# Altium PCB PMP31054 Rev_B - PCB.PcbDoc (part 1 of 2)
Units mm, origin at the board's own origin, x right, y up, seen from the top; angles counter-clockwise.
Board outline 89.28 x 61.72 mm, 4 copper layers (Top Layer, GND, Signal Layer 2, Bottom Layer), stack 2.134 mm thick; 58 components, 20 nets, 96 pads, 56 vias.
Unrouted connection lines stored in the file: 4.
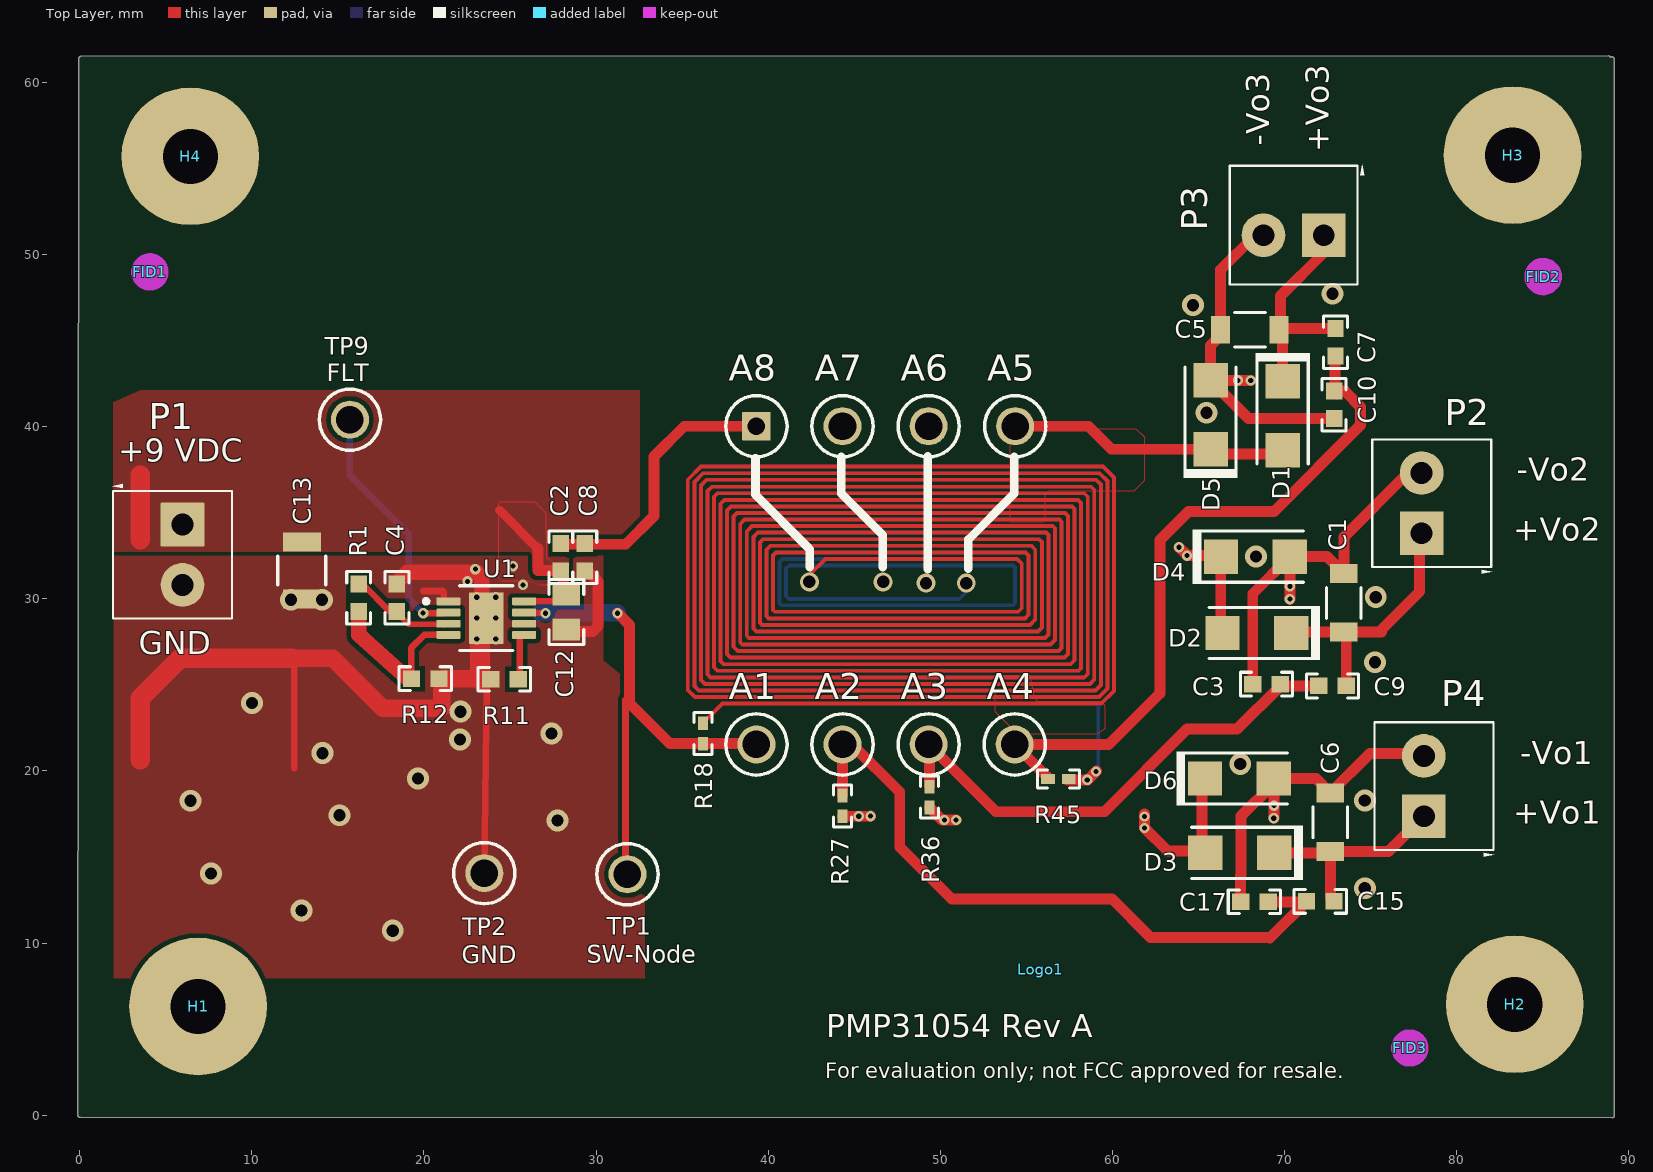
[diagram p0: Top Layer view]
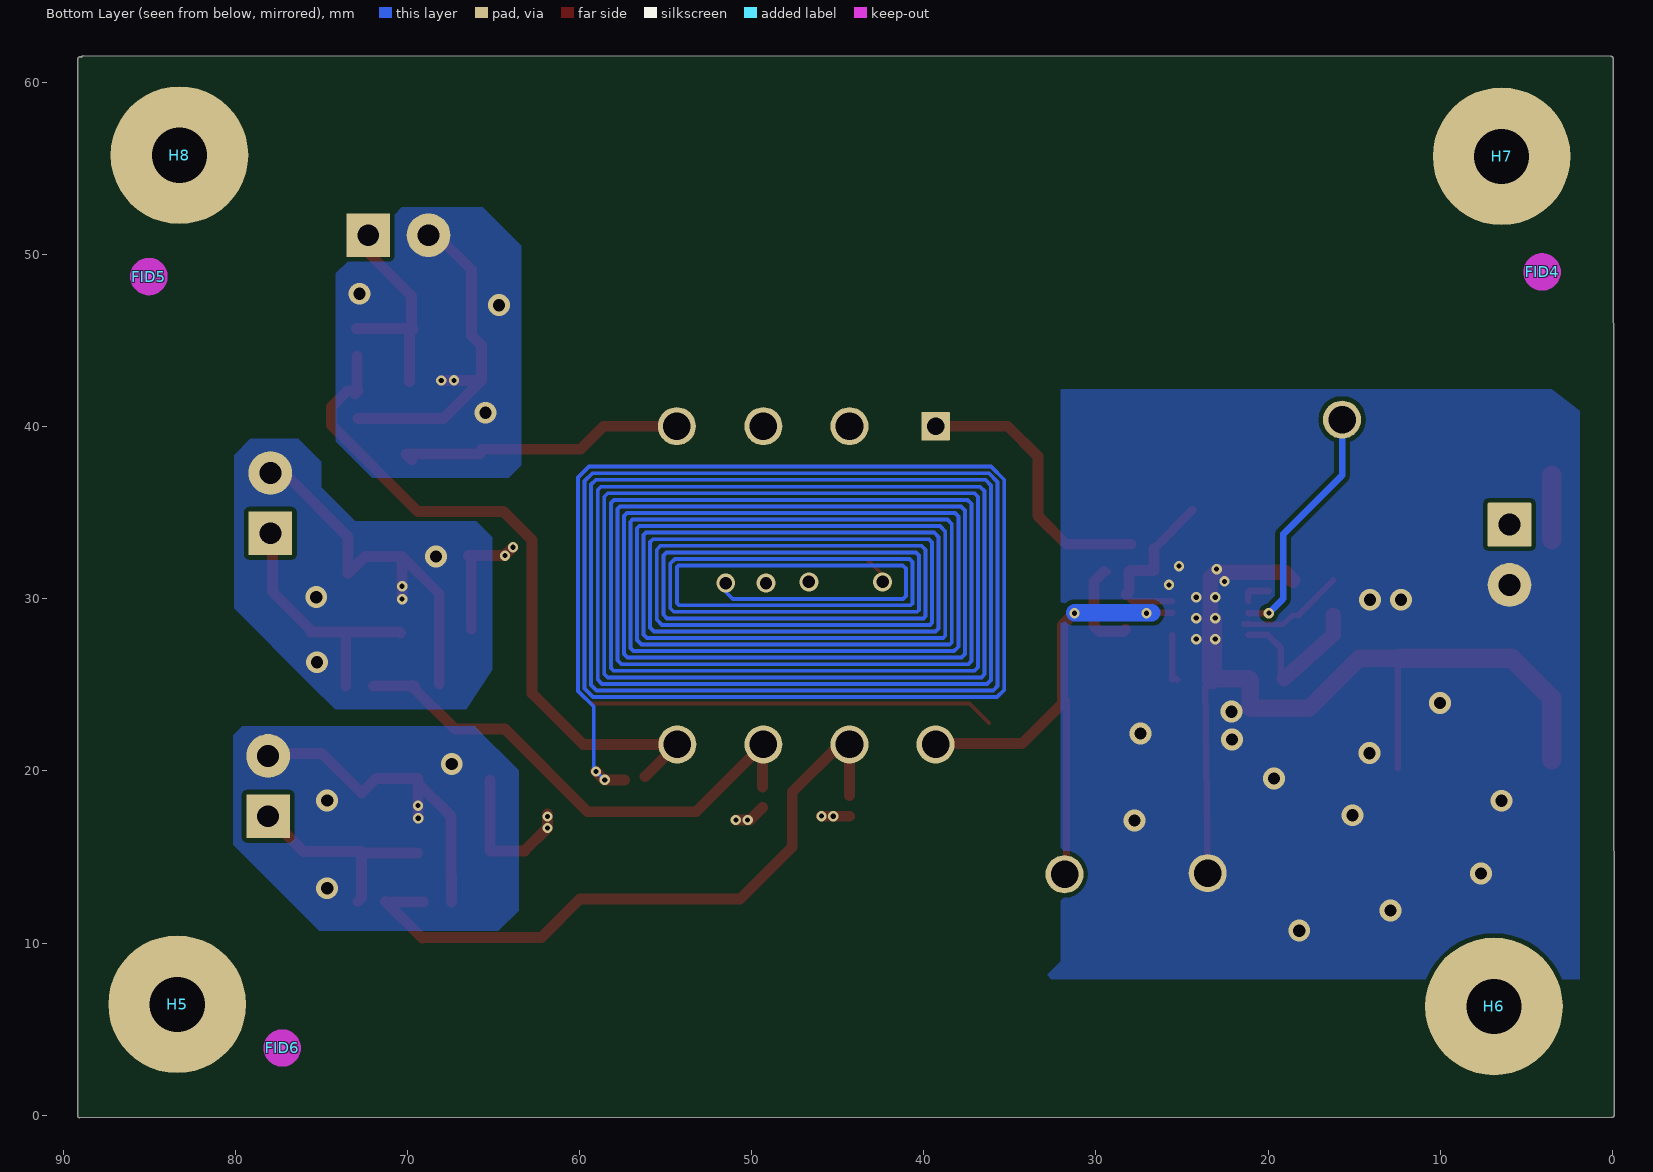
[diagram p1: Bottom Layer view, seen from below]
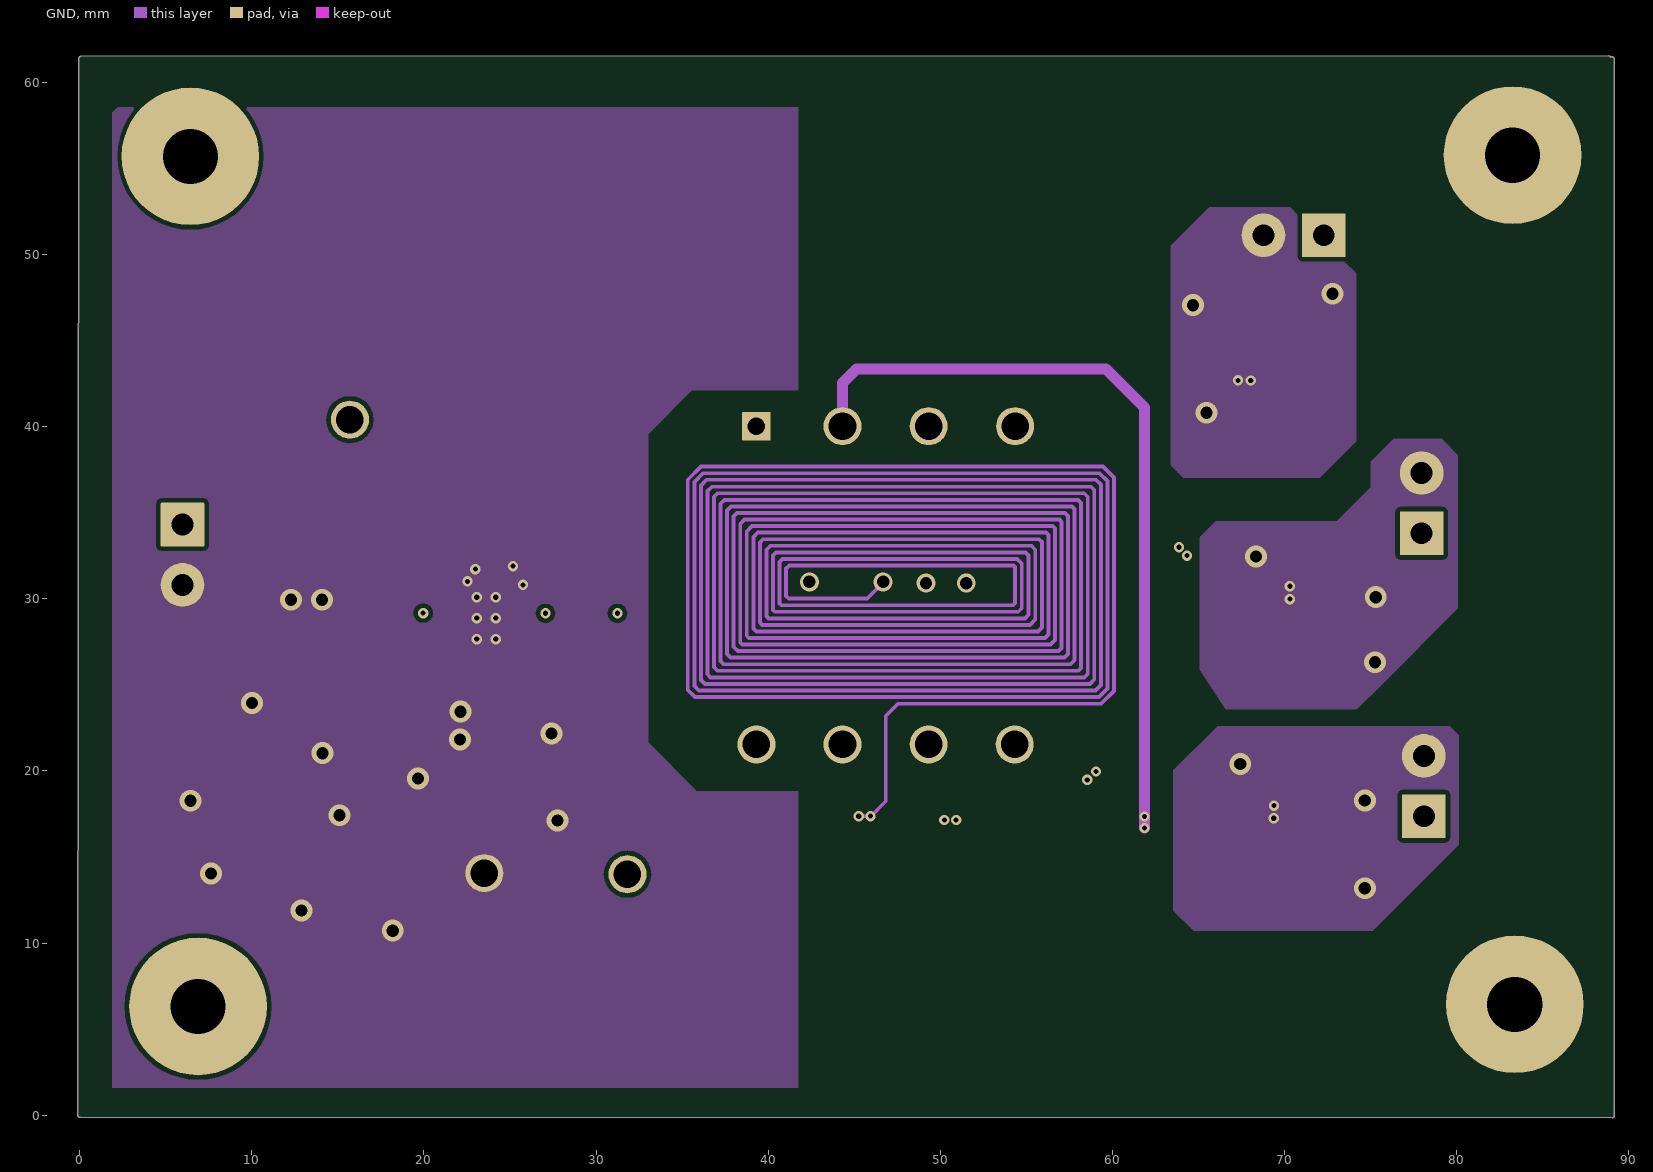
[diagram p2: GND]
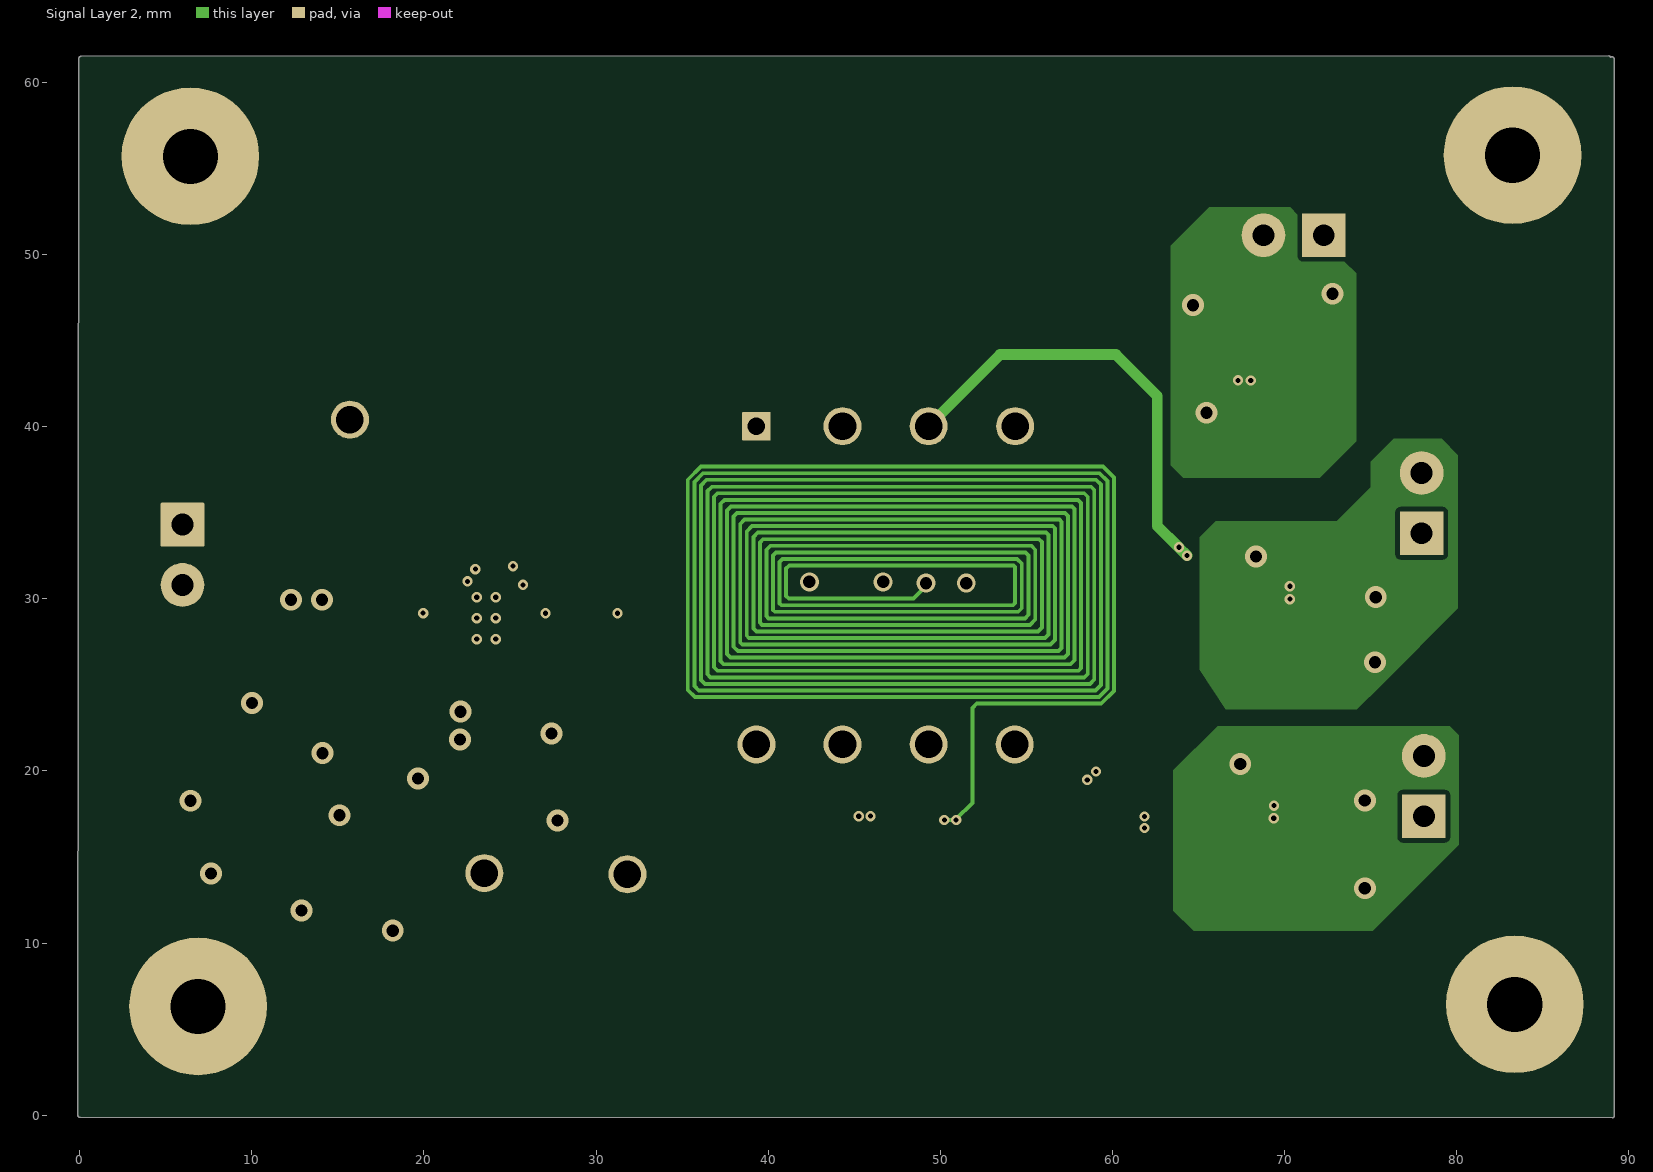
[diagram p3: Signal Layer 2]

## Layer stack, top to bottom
Top Solder: solder mask 0.0102, Solder Resist, Dk 3.5
Top Layer: signal copper 0.0356
Dielectric1: core 1.4834, FR-4 High Tg, Dk 4.8
GND: signal copper 0.036
Dielectric 2: dielectric 0.254, Dk 4.2
Signal Layer 2: signal copper 0.036
Dielectric 3: dielectric 0.254, Dk 4.2
Bottom Layer: signal copper 0.0356
Bottom Solder: solder mask 0.0102, Solder Resist, Dk 3.5

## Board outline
-0.116,-0.004 ccw(c0.011,-0.004) 0.011,-0.131 89.04,-0.165 ccw(c89.04,-0.038) 89.167,-0.038 89.167,61.366 ccw(c89.04,61.366) 88.959,61.465 ccw(c88.837,61.43) 88.836,61.557 0.075,61.523 ccw(c0.075,61.396) -0.053,61.396

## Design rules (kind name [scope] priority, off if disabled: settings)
AcuteAngle [All] p1: minimum=4.50000000000000E+0001 checktracksonly=FALSE
AssemblyTestPointUsage [All] p1: valid=2
BoardOutlineClearance BoardOutlineClearance_MountingHoles [OnCopper and InComponentClass('Mounting Holes')] p1: gap=1.016 ignorepadtopadclearanceinfootprint=FALSE
BoardOutlineClearance BoardOutlineClearance_Poly [OnCopper and IsPoly] p2: gap=0.635 ignorepadtopadclearanceinfootprint=FALSE except(0.254: Arc-CutoutEdge Track-CutoutEdge SMDPad-CutoutEdge THPad-CutoutEdge Via-CutoutEdge Fill-CutoutEdge Poly-CutoutEdge Region-CutoutEdge Text-CutoutEdge)
BoardOutlineClearance [OnCopper and Not InComponentClass('Logo') and not InComponentClass('FiducialMark') and not InRegion(1000,500,4000,800) and not InPoly] p3: gap=1.27 ignorepadtopadclearanceinfootprint=FALSE
Clearance Clearance_Keepouts [((IsTrack Or IsArc) And Not InPoly) And IsFree and IsKeepOut vs ((IsTrack Or IsArc) And Not InPoly) And IsFree and IsKeepOut] p1: gap=0 ignorepadtopadclearanceinfootprint=FALSE
Clearance Clearance_Poly [InPolygon] p2: gap=0.254 ignorepadtopadclearanceinfootprint=FALSE
Clearance Clearance_FiducialMark [IsKeepOut and InComponentClass('FiducialMark') vs IsPad and InComponentClass('FiducialMark')] p3: gap=0 ignorepadtopadclearanceinfootprint=FALSE
Clearance [All] p4: gap=0.2 ignorepadtopadclearanceinfootprint=FALSE except(0: Arc-Hole Track-Hole SMDPad-Hole THPad-Hole Via-Hole Fill-Hole Poly-Hole Region-Hole Text-Hole)
ComponentClearance ComponentClearance_NetTie [InComponent('NT1') vs HasFootprint('DSS0012C')] p1: gap=0 collisioncheckmode=3 verticalgap=0 showdistances=FALSE
ComponentClearance ComponentClearance_MountingHoles_FiducialMarks [InComponentClass('Mounting Holes') vs InComponentClass('FiducialMark')] p2: gap=1.27 collisioncheckmode=3 verticalgap=0.254 showdistances=FALSE
ComponentClearance ComponentClearance_Shunt [InComponentClass('Header') vs InComponentClass('Shunt')] p3: gap=0 collisioncheckmode=3 verticalgap=0 showdistances=FALSE
ComponentClearance ComponentClearance_Logo [InComponentClass('Logo')] p4: gap=1.27 collisioncheckmode=3 verticalgap=0.254 showdistances=FALSE
ComponentClearance ComponentClearance_ScrewToNut [(HasFootprint('NY PMS 440 0025 PH')) vs (HasFootprint('Keystone_1902C'))] p5: gap=0.127 collisioncheckmode=3 verticalgap=0.254 showdistances=FALSE
ComponentClearance ComponentClearance_MountingHoles [InComponentClass('Mounting Holes')] p6: gap=2.54 collisioncheckmode=3 verticalgap=2540 showdistances=FALSE
ComponentClearance ComponentClearance_SmallPassives [HasFootprint('0201*') or HasFootprint('0402*') or HasFootprint('0508') or HasFootprint('0603*') or HasFootprint('0612') or HasFootprint('0805*') or HasFootprint('0815*') or HasFootprint('0830*') or HasFootprint('1206*') or HasFootprint('1210*') or HasFootprint('1808*') or HasFootprint('1812*') or HasFootprint('1825*') or HasFootprint('2010*') or HasFootprint('2220*') or HasFootprint('2225*') or HasFootprint('2512*') or HasFootprint('2728*') or HasFootprint('3518*') vs HasFootprint('0201*') or HasFootprint('0402*') or HasFootprint('0508') or HasFootprint('0603*') or HasFootprint('0612') or HasFootprint('0805*') or HasFootprint('0815*') or HasFootprint('0830*') or HasFootprint('1206*') or HasFootprint('1210*') or HasFootprint('1808*') or HasFootprint('1812*') or HasFootprint('1825*') or HasFootprint('2010*') or HasFootprint('2220*') or HasFootprint('2225*') or HasFootprint('2512*') or HasFootprint('2728*') or HasFootprint('3518*')] p7: gap=0.38 collisioncheckmode=3 verticalgap=0.254 showdistances=FALSE
ComponentClearance ComponentClearance_THtoSMT [IsThruComponent vs IsSMTComponent] p8: gap=0.508 collisioncheckmode=3 verticalgap=0.762 showdistances=FALSE
ComponentClearance ComponentClearance_THtoTH [IsThruComponent vs IsThruComponent] p9: gap=0.508 collisioncheckmode=3 verticalgap=0.762 showdistances=FALSE
ComponentClearance [All] p10: gap=0.762 collisioncheckmode=3 verticalgap=0.254 showdistances=FALSE
DiffPairsRouting [All] p1: maxlimit=2.54 minlimit=0.254 mostfreqgap=0.254 toplayer_minwidth=0.381 toplayer_maxwidth=0.381 toplayer_prefwidth=0.381 midlayer1_minwidth=0.381 midlayer1_maxwidth=0.381 midlayer1_prefwidth=0.381 midlayer2_minwidth=0.381 midlayer2_maxwidth=0.381 midlayer2_prefwidth=0.381 bottomlayer_minwidth=0.381 bottomlayer_maxwidth=0.381 bottomlayer_prefwidth=0.381 maxuncoupledlength=25.4
FabricationTestPointUsage TestPointUsage [All] p1: valid=2 allowmultiple=FALSE
FabricationTestpoint Testpoint [All] p1: side=3 testpointundercomponent=TRUE minsize=1.016 maxsize=2.54 preferedsize=1.524 minholesize=0 maxholesize=1.016 preferedholesize=0.813 testpointgrid=0.025 allowsidetop=TRUE allowsidebottom=TRUE usegrid=TRUE gridtolerance=0
FanoutControl Fanout_LCC [IsLCC] p1: bgadir=Out bgaviamode=Centered fanoutstyle=Auto fanoutdirection=Alternating viagrid=0.025 // Fanout_LCC (Default Rule)
FanoutControl Fanout_BGA [IsBGA] p2: bgadir=Out bgaviamode=Centered fanoutstyle=Auto fanoutdirection=Alternating viagrid=0.025 // Fanout_BGA (Default Rule)
FanoutControl Fanout_Default [All] p4: bgadir=Out bgaviamode=Centered fanoutstyle=Auto fanoutdirection=Alternating viagrid=0.025 // Fanout_Default (Default Rule)
FanoutControl Fanout_Small [(CompPinCount < 5)] p5: bgadir=Out bgaviamode=Centered fanoutstyle=Auto fanoutdirection=OutThenIn viagrid=0.025 // Fanout_Small (Default Rule)
HoleSize [All] p1: absolutevalues=TRUE maxlimit=6.375 minlimit=0.3 maxpercent=80.000 minpercent=20.000
MinimumAnnularRing MinimumAnnularRing_ThermalPadVias [IsVia and InAnyComponent] p1: minimumring=0.15
MinimumAnnularRing [All] p2: minimumring=0.15
MinimumSolderMaskSliver MinimumSolderMaskSliver_Logo [InComponentClass('Logo') vs InComponentClass('Logo')] p1: minsoldermaskwidth=0.018
MinimumSolderMaskSliver [All] p2: minsoldermaskwidth=0.1
PlaneConnect [All] p1: planeconnectstyle=Relief reliefexpansion=0.254 reliefentries=4 reliefconductorwidth=0.254 reliefairgap=0.254
PolygonConnect [All] p1: connectstyle=Direct reliefconductorwidth=0.254 reliefentries=4 polygonreliefangle="90 Angle" airgapwidth=0.254
RoutingVias ThermalPadVias [IsVia and InAnyComponent] p1: holewidth=0.2 width=0.5 viastyle="Through Hole" minholewidth=0.2 minwidth=0.5 maxholewidth=0.33 maxwidth=0.6
RoutingVias [All] p2: holewidth=0.254 width=0.559 viastyle="Through Hole" minholewidth=0.2 minwidth=0.508 maxholewidth=1.016 maxwidth=1.651
SilkToBoardRegionClearance [Not ((IsComment or IsDesignator) And (Hide <> 'False')) and not InRegion(1000,500,4000,800)] p1:
SilkToSilkClearance SilkToSilkClearance_Pb-FreeLogo [(HasFootprint('Pb-Free_Overlay_Medium') OR HasFootprint('Pb-Free_Overlay_Small')) vs (HasFootprint('Pb-Free_Overlay_Medium') OR HasFootprint('Pb-Free_Overlay_Small'))] p1: silktosilkclearance=0
SilkToSilkClearance [All] p2: silktosilkclearance=0.102
SilkToSolderMaskClearance SilkToComponentPadClearance [(IsPad or IsFill or IsRegion) and InAnycomponent] p1: minsilkscreentomaskgap=0 clearancetoexposedcopper=TRUE
SilkToSolderMaskClearance "Silk to Solder Mask Opening" [All] p2: minsilkscreentomaskgap=0.102 clearancetoexposedcopper=FALSE
SolderMaskExpansion [All] p1: expansion=0.05 istentingtop=FALSE
Width [All] p1: maxlimit=2.54 minlimit=0.203 preferedwidth=0.381 checkconnectedcopper=TRUE
15 further rules are at their usual default settings.

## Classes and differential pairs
component class FiducialMark: FID1 FID2 FID3 FID4 FID5 FID6
component class "Mounting Holes": H1 H2 H3 H4
component class "PMP31054 Rev_B - hardware": !PCB FID1 FID2 FID3 FID4 FID5 FID6 H1 H2 H3 H4 H5 H6 H7 H8 LBL1 Logo1 Logo5
component class "PMP31054 Rev_B Sheet1": A1 A2 A3 A4 A5 A6 A7 A8 C1 C2 C3 C4 C5 C6 C7 C8 C9 C10 C12 C13 C15 C17 D1 D2 D3 D4 D5 D6 P1 P2 P3 P4 R1 R11 R12 R18 R27 R36 R45 TP1 TP2 TP9 U1

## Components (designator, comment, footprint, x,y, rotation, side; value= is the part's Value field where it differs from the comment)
A1 "5010" Keystone5010#1 39.319,21.539 r0 top
A2 "5010" Keystone5010#1 44.323,21.539 r0 top
A3 "5010" Keystone5010#1 49.327,21.539 r0 top
A4 "5010" Keystone5010#1 54.331,21.539 r0 top
A5 "5010" Keystone5010#1 54.356,40.03 r0 top
A6 "5010" Keystone5010#1 49.327,40.03 r0 top
A7 "5010" Keystone5010#1 44.323,40.03 r0 top
A8 "5010" Keystone5010#2 39.319,40.03 r0 top
C1 "885012108022" 1206_180 73.457,29.767 r90 top value=10uF
C2 "GRM188R71H153KA01D" 0603 27.953,32.41 r90 top value=0.015uF
C3 "CL10B822KB8NNNC" 0603 72.796,24.943 r180 top value=8200pF
C4 "C1608X7R1E105K080AB" 0603 18.428,30.061 r90 top value=1uF
C5 "885012108022" 1206_180 67.996,45.644 r180 top value=10uF
C6 "885012108022" 1206_180 72.669,17.018 r90 top value=10uF
C7 "CL10B822KB8NNNC" 0603 72.974,44.907 r270 top value=8200pF
C8 "GRM188R71H153KA01D" 0603 29.35,32.41 r270 top value=0.015uF
C9 "CL10B822KB8NNNC" 0603 68.961,25.044 r180 top value=8200pF
C10 "CL10B822KB8NNNC" 0603 72.89,41.275 r270 top value=8200pF
C12 "CGA4J3X7R1H225K125AB" 0805_HV 28.27,29.235 r270 top value=2.2uF
C13 "885012209073" 1210_280 12.903,31.648 r270 top value=10uF
C15 "CL10B822KB8NNNC" 0603 72.085,12.421 r180 top value=8200pF
C17 "CL10B822KB8NNNC" 0603 68.262,12.395 r180 top value=8200pF
D1 "CMSH1-40M TR13" SMA 69.901,40.64 r270 top value=40V
D2 "CMSH1-40M TR13" SMA 68.402,28.016 r180 top value=40V
D3 "CMSH1-40M TR13" SMA 67.412,15.24 r180 top value=40V
D4 "CMSH1-40M TR13" SMA 68.319,32.451 r0 top value=40V
D5 "CMSH1-40M TR13" SMA 65.71,40.691 r90 top value=40V
D6 "CMSH1-40M TR13" SMA 67.386,19.558 r0 top value=40V
FID1 "Fiducial" Fiducial6.4-20 4.077,48.997 r0 top
FID2 "Fiducial" Fiducial6.4-20 85.039,48.73 r0 top
FID3 "Fiducial" Fiducial6.4-20 77.292,3.899 r0 top
FID4 "Fiducial" Fiducial6.4-20 4.077,48.997 r180 bottom
FID5 "Fiducial" Fiducial6.4-20 85.039,48.73 r180 bottom
FID6 "Fiducial" Fiducial6.4-20 77.292,3.899 r180 bottom
H1 "NY PMS 440 0025 PH" "NY PMS 440 0025 PH" 6.871,6.312 r0 top
H2 "NY PMS 440 0025 PH" "NY PMS 440 0025 PH" 83.388,6.439 r0 top
H3 "NY PMS 440 0025 PH" "NY PMS 440 0025 PH" 83.261,55.778 r0 top
H4 "NY PMS 440 0025 PH" "NY PMS 440 0025 PH" 6.426,55.715 r0 top
H5 "1902C" Keystone_1902C 83.388,6.439 r180 bottom
H6 "1902C" Keystone_1902C 6.871,6.312 r180 bottom
H7 "1902C" Keystone_1902C 6.426,55.715 r180 bottom
H8 "1902C" Keystone_1902C 83.261,55.778 r180 bottom
Logo1 "FCC disclaimer" FCC_disclaimer 55.829,8.471 r0 top locked
P1 "ED555/2DS" TERM_BLK_ED555-2DS 5.969,34.315 r270 top
P2 "ED555/2DS" TERM_BLK_ED555-2DS 77.978,33.807 r90 top
P3 "ED555/2DS" TERM_BLK_ED555-2DS 72.288,51.13 r180 top
P4 "ED555/2DS" TERM_BLK_ED555-2DS 78.105,17.367 r90 top
R1 "CRCW06032K49FKEA" 0603 16.205,30.061 r90 top value=2.49k
R11 "CRCW0603100KFKEA" 0603 24.676,25.324 r0 top value=100k
R12 "CRCW06032K49FKEA" 0603 20.079,25.362 r180 top value=2.49k
R18 "ERJ2BWFR100X" 0402 36.22,22.174 r270 top value=0.1
R27 "ERJ2BWFR100X" 0402 44.323,17.967 r90 top value=0.1
R36 "ERJ2BWFR100X" 0402 49.378,18.475 r90 top value=0.1
R45 "ERJ2BWFR100X" 0402 56.871,19.533 r180 top value=0.1
TP1 "5010" Keystone5010#1 31.826,13.995 r90 top
TP2 "5011" Keystone5011 23.508,14.059 r90 top
TP9 "5010" Keystone5010#1 15.697,40.411 r0 top
U1 "UCC25800DGNRQ1" DGN0008G-MFG 23.622,28.877 r0 top

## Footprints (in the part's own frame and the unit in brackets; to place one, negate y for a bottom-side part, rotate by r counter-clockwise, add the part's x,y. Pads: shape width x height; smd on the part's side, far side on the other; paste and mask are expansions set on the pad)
0402 [mm] "0402 from SM-752 data"
  rect 0.8x0.6 smd: 1(-0.6,0) 2(0.6,0)
  silkscreen extent -1.22,-0.52 1.22,0.52, body extent -0.55,-0.3 0.55,0.3, height 0.6
0603 [mm] "0603 from SM-752 data"
  rect 1x0.95 smd: 1(-0.8,0) 2(0.8,0)
  silkscreen extent -1.52,-0.69 1.52,0.69, body extent -0.87,-0.47 0.87,0.47, height 1
0805_HV [mil] "0805 with 30mil clearance between pads"
  rect 50x63 smd: 1(-40,0) 2(40,0)
  silkscreen extent -74,-40 74,40, body extent -43,-29 43,29, height 57
1206_180 [mm] "1206_180"
  rect 1.1x1.6 smd: 1(-1.7,0) 2(1.7,0)
  silkscreen extent -0.9,-1 0.9,1, body extent -1.75,-0.95 1.75,0.95, height 1.8
1210_280 [mm] "SMD, 2-Leads, Body 3.6x2.8mm, Height 2.8mm"
  rect 1.1x2.2 smd: 1(-1.65,0) 2(1.65,0)
  silkscreen extent -0.84,-1.4 0.84,1.4, body extent -1.8,-1.4 1.8,1.4, height 2.8
DGN0008G-MFG [mm]
  rrect22% 1.4x0.45 smd paste+0 mask+0: 1(-2.2,0.975) 2(-2.2,0.325) 3(-2.2,-0.325) 4(-2.2,-0.975) 5(2.2,-0.975) 6(2.2,-0.325) 7(2.2,0.325) 8(2.2,0.975)
  rrect5% 2x3 smd paste-1000 mask-1000: 9(0,0)
  silkscreen extent -3.62,-1.88 1.55,1.88, body extent -3,-1.8 3,1.8, height 0.25
FCC_disclaimer [mm]
Fiducial6.4-20 [mm]
  round 0.635 smd mask+0.683: 1(0,0)
  Top Layer keep-out circle w1.178: c0,0 r0.5
Keystone5010#1 [mil] "Keystone Multipurpose loops"
  round 87 hole 63: 1(0,0)
  silkscreen extent -70,-70 70,70, body extent -63,-63 63,62, height 319
Keystone5010#2 [mil] "Keystone Multipurpose loops"
  rrect6% 64.96x64.96 hole 40: 1(0,0)
  silkscreen extent -70,-70 70,70, body extent -63,-63 63,62, height 319
Keystone5011 [mil] "Keystone Multipurpose loops"
  round 87 hole 63: 1(0,0)
  silkscreen extent -70,-70 70,70, body extent -63,-63 63,62, height 319
Keystone_1902C [mil] "Hex Standoff, 4-40 threaded, nylon"
  round 1 on Mech4: 0(0,0)
  body extent -145,-126 146,126, height 501
"NY PMS 440 0025 PH" [mm] "4-40 nylon screw and mounting hole"
  round 8 hole 3.2: 1(0,0)
  body extent -3.3,-3.3 3.3,3.3, height 2.69
SMA [mm] "Molded Diode, 2-Leads, Body 4.3x2.6mm, IPC Medium Density, based on OnSemi component dimensions and land pattern"
  rect 2x2 smd: 1(-2,0) 2(2,0)
  silkscreen extent -3.66,-1.57 2.79,1.57, body extent -2.6,-1.3 2.6,1.3, height 2.42
TERM_BLK_ED555-2DS [mil]
  rrect4% 100x100 hole 50: 1(0,0)
  round 100 hole 50: 2(138,0)
  silkscreen extent -93,-161 215,113, body extent -69,-150 207,106, height 323

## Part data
A1 A2 A3 A4 A5 A6 A7 A8 TP1 TP9: library part CMP-0055147-1, "Test Point, Multipurpose, Red, TH", Color=Red, Manufacturer=Keystone, Supplier Part Number 1=36-5010-ND
C1 C5 C6: library part CMP-0081454-1, "CAP, CERM, 10 µF, 50 V,+/- 20%, X5R, 1206", Cap_Case=1206, Manufacturer="Wurth Elektronik", TempCo=X5R, Tolerance_%=20%, Value2=50V, ValueDisplayed=10µF
C2 C8: library part CMP-0007438-4, "CAP, CERM, 0.015 uF, 50 V, +/- 10%, X7R, 0603", Cap_Case=0603, Manufacturer=MuRata, Supplier Part Number 1=490-1514-1-ND, TempCo=X7R, Tolerance_%=10%, Value1=Unknown, Value2=50V, ValueDisplayed=0.015uF
C3 C7 C9 C10 C15 C17: library part CMP-0860998-1, "CAP, CERM, 8200 pF, 50 V,+/- 10%, X7R, 0603", Cap_Case=0603, Manufacturer="Samsung Electro-Mechanics", TempCo=X7R, Tolerance_%=10%, Value2=50V, ValueDisplayed=8200pF
C4: library part CMP-0007040-4, "CAP, CERM, 1 uF, 25 V, +/- 10%, X7R, 0603", Cap_Case=0603, Manufacturer=TDK, Supplier Part Number 1=445-5956-1-ND, TempCo=X7R, Tolerance_%=10%, Value1=Unknown, Value2=25V, ValueDisplayed=1uF
C12: library part CMP-0007977-1, "CAP, CERM, 2.2 uF, 50 V, +/- 10%, X7R, AEC-Q200 Grade 1, 0805", Cap_Case=0805, Manufacturer=TDK, Supplier Part Number 1=445-174216-1-ND, TempCo=X7R, Tolerance_%=10%, Value1="0.003288 ohm", Value2=50V, ValueDisplayed=2.2uF
C13: library part CMP-0085350-1, "CAP, CERM, 10 µF, 50 V,+/- 10%, X7S, AEC-Q200 Grade 1, 1210", Cap_Case=1210, Manufacturer=TDK, PartNumber=CGA6P3X7S1H106K250AE, TempCo=X7S, Tolerance_%=10%, Value2=50V, ValueDisplayed=10µF
D1 D2 D3 D4 D5 D6: library part CMP-0028785-1, "Diode Schottky 40V 1A Surface Mount SMA", Manufacturer="Diodes Inc.", Value1=3A, Value2=0.7V
FID1 FID2 FID3 FID4 FID5 FID6: library part CMP-0077181-1, "Fiducial mark.  There is nothing to buy or mount.", Manufacturer=N/A
H1 H2 H3 H4: library part CMP-0003617-1, "Machine Screw, Round, #4-40 x 1/4, Nylon, Philips panhead", Manufacturer="B&F Fastener Supply", Supplier Part Number 1=H542-ND
H5 H6 H7 H8: library part CMP-0003610-1, "Standoff, Hex, 0.5\"L #4-40 Nylon", Manufacturer=Keystone, Supplier Part Number 1=36-1902C-ND
Logo1: library part CMP-0074847-1, "FCC_disclaimer"
P1 P2 P3 P4: library part CMP-0074913-1, "Terminal Block, 3.5mm Pitch, 2x1, TH", Color=Grey, Current_A=6A, Manufacturer="On-Shore Technology", Supplier Part Number 1=ED1514-ND, Voltage_V=150V
R1 R12: library part CMP-0022277-4, "RES, 2.49 k, 1%, 0.1 W, AEC-Q200 Grade 0, 0603", Manufacturer=Vishay-Dale, Power_W=100mW, Supplier Part Number 1=541-2.49KHCT-ND, TempCo="100 ppm/C", Tolerance_%=1%, Value2=0.1W, Value_Code=2k49, ValueDisplayed=2.49k
R11: library part CMP-0021990-4, "RES, 100 k, 1%, 0.1 W, AEC-Q200 Grade 0, 0603", Manufacturer=Vishay-Dale, Power_W=100mW, Supplier Part Number 1=541-100KHCT-ND, TempCo="100 ppm/C", Tolerance_%=1%, Value2=0.1W, Value_Code=100k
R18 R27 R36 R45: library part CMP-0078660-1, "RES, 0.1, 1%, 0.25 W, 0402", Manufacturer=Panasonic, Power_W=250mW, Supplier Part Number 1=P17368CT-ND, TempCo="300 ppm/C", Tolerance_%=1%, Value2=0.25W, Value_Code=R100, ValueDisplayed=0.1
TP2: library part CMP-0055148-1, "Test Point, Multipurpose, Black, TH", Color=Black, Manufacturer=Keystone, Supplier Part Number 1=36-5011-ND
U1: library part CMP-0088494-2, "Open Loop LLC Transformer Driver for Isolated Bias Supplies", Manufacturer="Texas Instruments", Max Supply Voltage=36V, Min Supply Voltage=12V, Nominal Supply Current=500uA, Operating Temperature Range="-40°C to +150°C", Switching Frequency=100-2000kHz

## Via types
v1: diameter 0.6, hole 0.3, Top Layer to Bottom Layer, 29 vias
v2: diameter 1.27, hole 0.711, Top Layer to Bottom Layer, 23 vias
v3: diameter 1.1, hole 0.71, Top Layer to Bottom Layer, 4 vias

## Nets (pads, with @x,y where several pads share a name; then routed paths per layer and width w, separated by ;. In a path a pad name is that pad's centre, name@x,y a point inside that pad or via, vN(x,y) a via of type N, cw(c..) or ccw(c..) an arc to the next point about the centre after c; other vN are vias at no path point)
GND: C4.2 C8.2 C12.2 C13.2 P1.2 R11.1 R12.1 TP2.1 U1.1 U1.6 U1.9 | length 64
  Top Layer w0.381: 12.331,26.545 12.459,26.417 12.459,20.145 ; C4.2@18.428,31.077 C4.2@18.555,31.077 ; 19.952,30.455 21.082,30.455 21.158,30.378 U1.1@21.158,29.852 ; 21.012,23.647 21.031,23.666 ; R12.1@21.031,25.298 R12.1@21.095,25.362 ; 23.19,25.362 23.254,25.298 23.644,24.908 TP2.1@23.508,14.059 ; U1.9@23.358,28.877 23.254,28.772 U1.9@23.474,28.552 ; C8.2@29.286,31.585 C8.2@29.54,31.585
  Top Layer w0.635: C12.2@28.27,28.219 28.397,28.092 29.794,28.092 30.112,28.41 30.112,31.013 C8.2@29.54,31.585
  Top Layer w0.889: C4.2@18.555,31.077 19.023,31.545 21.095,31.545 23.063,31.545 23.358,31.25 U1.9@23.358,28.877
  Top Layer w1.016: 12.331,26.545 14.705,26.545 17.602,23.647 21.012,23.647 ; 21.031,23.666 R12.1@21.031,25.298 ; R12.1@21.095,25.362 23.19,25.362
  Top Layer w1.143: 3.505,20.663 3.505,24.219 5.831,26.545 12.331,26.545 ; 23.254,25.298 U1.9@23.254,28.772
  other v1: 23.072,27.657 24.172,27.657 23.072,28.877 24.172,28.877 23.072,30.097 24.172,30.097 25.756,30.81 22.53,31.013 22.987,31.725 25.171,31.902
  other v2: 18.186,10.719 12.878,11.887 7.62,14.046 27.762,17.12 15.088,17.424 6.426,18.263 19.66,19.558 14.097,21.031 22.098,21.819 27.407,22.174 22.123,23.444 10.008,23.952 12.281,29.947 14.072,29.947
NetA1_1: A1.1 R18.2 TP1.1 U1.7 | length 30.1
  Top Layer w0.381: U1.7@25.558,29.202 U1.7@25.822,29.202 26.746,29.202 ; TP1.1@31.826,13.995 31.711,14.11 31.711,24.142 31.953,24.384 ; A1.1@39.194,21.582 39.278,21.498 A1.1@39.319,21.539
  Top Layer w0.5: v1(31.245,29.159) v1@31.258,29.172
  Top Layer w0.635: v1@31.258,29.172 31.953,28.477 31.953,24.52 31.953,24.384 ; 31.953,24.296 31.953,23.936 34.307,21.582 A1.1@39.194,21.582
  Bottom Layer w1.016: 26.746,29.202 v1@31.245,29.202
  other v1: 27.064,29.159
NetA2_1: A2.1 C15.2 C17.1 R27.2 | length 39.2
  Top Layer w0.635: R27.2@44.323,18.567 A2.1@44.323,21.539 44.882,21.539 47.65,18.771 47.65,15.57 50.673,12.548 59.995,12.548 62.23,10.312 69.177,10.312 ; C17.1@69.062,12.395 C15.2@70.942,12.395 ; 69.151,10.287 69.177,10.312 ; C15.2@71.285,12.421 69.177,10.312
NetA3_1: A3.1 C3.2 C9.1 R36.2 | length 29.9
  Top Layer w0.635: A3.1@49.327,21.539 A3.1@49.378,21.488 ; R36.2@49.378,19.075 A3.1@49.378,21.488 ; C9.1@69.596,24.943 C9.1@69.767,24.943 ; C9.1@69.787,24.963 C9.1@69.767,24.943 ; C3.2@71.996,24.943 C9.1@69.767,24.943 ; A3.1@49.378,21.488 53.238,17.628 59.538,17.628 64.338,22.428 67.252,22.428 C9.1@69.767,24.943
NetA4_1: A4.1 C7.2 C10.1 R45.2 | length 41.1
  Top Layer w0.225: R45.2@56.194,19.482 R45.2@56.194,19.675
  Top Layer w0.635: R45.2@56.194,19.675 A4.1@54.331,21.539 59.792,21.539 62.763,24.511 62.763,33.415 64.426,35.077 69.409,35.077 74.43,40.099 74.43,41.156 73.511,42.075 C10.1@73.055,42.075 ; C7.2@72.949,44.107 72.949,42.181 C10.1@73.055,42.075 ; C10.1@73.056,41.909 C10.1@72.89,42.075 C10.1@73.055,42.075
NetA5_1: A5.1 D1.2 D5.1 R45.1 | length 868.5
  Top Layer w0.225: A5.1@54.007,39.681 A5.1@54.356,40.03
  Top Layer w0.635: A5.1@54.356,40.03 58.623,40.03 59.963,38.691 D5.1@65.71,38.691 ; R45.1@57.394,19.482 v1(58.547,19.482) 58.572,19.482 v1@59.08,19.99 ; D5.1@65.786,38.405 70.097,38.405 D1.2@69.748,38.056
  Bottom Layer w0.225: v3@51.587,31.217 51.664,31.14 51.511,30.988 v3(51.511,30.912) 51.511,30.404 51.105,29.997 41.213,29.997 41.046,30.164 41.046,31.764 41.224,31.942 54.254,31.942 54.356,31.84 54.356,29.758 54.228,29.63 40.767,29.63 40.665,29.732 40.665,32.145 40.843,32.323 54.458,32.323 54.737,32.043 54.737,29.452 54.534,29.249 40.386,29.249 40.284,29.351 40.284,32.526 40.462,32.704 54.96,32.704 55.138,32.526 55.138,29.077 54.93,28.868 40.03,28.868 39.903,28.995 39.903,32.856 40.132,33.085 55.296,33.085 55.524,32.856 55.524,28.792 55.22,28.487 39.649,28.487 39.522,28.614 39.522,33.284 39.702,33.464 55.751,33.464 55.905,33.309 55.905,28.335 55.677,28.106 39.319,28.106 39.141,28.284 39.141,33.593 39.395,33.847 56.147,33.847 56.286,33.707 56.286,27.928 56.083,27.725 38.887,27.725 38.76,27.852 38.76,33.923 39.065,34.228 56.54,34.228 56.667,34.101 56.667,27.598 56.413,27.344 38.506,27.344 38.379,27.471 38.379,34.355 38.633,34.609 56.921,34.609 57.048,34.482 57.048,27.141 56.871,26.963 38.252,26.963 37.998,27.217 37.998,34.786 38.202,34.99 57.252,34.99 57.429,34.812 57.429,26.785 57.226,26.582 37.821,26.582 37.617,26.785 37.617,35.142 37.846,35.371 57.658,35.371 57.81,35.218 57.81,26.43 57.582,26.201 37.414,26.201 37.236,26.379 37.236,35.525 37.461,35.75 58.014,35.75 58.191,35.572 58.191,25.973 58.039,25.82 37.059,25.82 36.855,26.023 36.855,35.929 37.059,36.133 58.369,36.133 58.572,35.929 58.572,25.642 58.369,25.439 36.652,25.439 36.474,25.617 36.474,36.26 36.728,36.514 58.776,36.514 58.953,36.336 58.953,25.312 58.699,25.058 36.322,25.058 36.093,25.287 36.093,36.59 36.424,36.92 59.055,36.92 59.334,36.641 59.334,24.982 59.03,24.677 35.966,24.677 35.715,24.928 35.715,36.796 36.216,37.296 59.263,37.296 59.715,36.844 59.715,24.779 59.233,24.296 35.741,24.296 35.331,24.706 35.331,36.92 36.093,37.682 59.461,37.682 60.096,37.047 60.096,24.652 59.182,23.737 59.182,20.117 v1(58.547,19.482)
  other v1: 59.055,19.964
NetA6_1: A6.1 D2.2 D4.1 R36.1 | length 891.8
  Top Layer w0.225: D4.1@66.301,32.432 D4.1@66.319,32.451
  Top Layer w0.635: R36.1@49.378,17.875 50.108,17.145 v1(50.241,17.145) v1(50.927,17.145) ; v1(63.881,32.995) 64.338,32.537 v1(64.338,32.512) D4.1@66.478,32.512 ; D2.2@66.301,28.26 D4.1@66.301,32.432
  Signal Layer 2 w0.225: v3(49.174,30.912) 49.174,30.736 48.449,30.011 41.199,30.011 41.046,30.164 41.046,31.764 41.224,31.942 54.254,31.942 54.356,31.84 54.356,29.758 54.228,29.63 40.767,29.63 40.665,29.732 40.665,32.145 40.843,32.323 54.458,32.323 54.737,32.043 54.737,29.452 54.534,29.249 40.386,29.249 40.284,29.351 40.284,32.526 40.462,32.704 54.96,32.704 55.138,32.526 55.138,29.077 54.93,28.868 40.03,28.868 39.903,28.995 39.903,32.856 40.132,33.085 55.296,33.085 55.524,32.856 55.524,28.792 55.22,28.487 39.649,28.487 39.522,28.614 39.522,33.284 39.702,33.464 55.751,33.464 55.905,33.309 55.905,28.335 55.677,28.106 39.319,28.106 39.141,28.284 39.141,33.593 39.395,33.847 56.147,33.847 56.286,33.707 56.286,27.928 56.083,27.725 38.887,27.725 38.76,27.852 38.76,33.923 39.065,34.228 56.54,34.228 56.667,34.101 56.667,27.598 56.413,27.344 38.506,27.344 38.379,27.471 38.379,34.355 38.633,34.609 56.921,34.609 57.048,34.482 57.048,27.141 56.871,26.963 38.252,26.963 37.998,27.217 37.998,34.786 38.202,34.99 57.252,34.99 57.429,34.812 57.429,26.785 57.226,26.582 37.821,26.582 37.617,26.785 37.617,35.142 37.846,35.371 57.658,35.371 57.81,35.218 57.81,26.43 57.582,26.201 37.414,26.201 37.236,26.379 37.236,35.525 37.461,35.75 58.014,35.75 58.191,35.572 58.191,25.973 58.039,25.82 37.059,25.82 36.855,26.023 36.855,35.929 37.059,36.133 58.369,36.133 58.572,35.929 58.572,25.642 58.369,25.439 36.652,25.439 36.474,25.617 36.474,36.26 36.728,36.514 58.776,36.514 58.953,36.336 58.953,25.312 58.699,25.058 36.322,25.058 36.093,25.287 36.093,36.59 36.424,36.92 59.055,36.92 59.334,36.641 59.334,24.982 59.03,24.677 35.966,24.677 35.715,24.928 35.715,36.796 36.216,37.296 59.263,37.296 59.715,36.844 59.715,24.779 59.233,24.296 35.741,24.296 35.331,24.706 35.331,36.92 36.093,37.682 59.461,37.682 60.096,37.047 60.096,24.652 59.36,23.915 52.121,23.915 51.867,23.661 51.867,18.136 50.927,17.196 v1(50.927,17.145) v1(50.241,17.145)
  Signal Layer 2 w0.635: A6.1@49.327,40.03 53.486,44.19 60.204,44.19 62.611,41.783 62.611,34.239 v1@63.868,32.982 ; v1(63.881,32.995) 63.881,32.969 v1(64.338,32.512)
NetA7_1: A7.1 D3.2 D6.1 R27.1 | length 915.4
  Top Layer w0.215: A7.1@44.323,39.827 A7.1@44.323,40.03
  Top Layer w0.225: D6.1@65.208,19.475 D6.1@65.24,19.507
  Top Layer w0.635: R27.1@44.323,17.367 v1@45.339,17.367 ; v1(45.263,17.367) 45.942,17.367 v1(45.949,17.374) ; v1@61.874,17.501 v1(61.874,16.688) 63.195,15.367 ; 63.195,15.342 65.208,15.342 D6.1@65.208,19.475
  GND w0.225: v1(45.263,17.367) 45.968,17.367 46.838,18.237 46.838,23.19 47.549,23.901 59.346,23.901 60.096,24.652 60.096,37.047 59.461,37.682 36.093,37.682 35.331,36.92 35.331,24.706 35.741,24.296 59.233,24.296 59.715,24.779 59.715,36.844 59.263,37.296 36.216,37.296 35.715,36.796 35.715,24.928 35.966,24.677 59.03,24.677 59.334,24.982 59.334,36.641 59.055,36.92 36.424,36.92 36.093,36.59 36.093,25.287 36.322,25.058 58.699,25.058 58.953,25.312 58.953,36.336 58.776,36.514 36.728,36.514 36.474,36.26 36.474,25.617 36.652,25.439 58.369,25.439 58.572,25.642 58.572,35.929 58.369,36.133 37.059,36.133 36.855,35.929 36.855,26.023 37.059,25.82 58.039,25.82 58.191,25.973 58.191,35.572 58.014,35.75 37.461,35.75 37.236,35.525 37.236,26.379 37.414,26.201 57.582,26.201 57.81,26.43 57.81,35.218 57.658,35.371 37.846,35.371 37.617,35.142 37.617,26.785 37.821,26.582 57.226,26.582 57.429,26.785 57.429,34.812 57.252,34.99 38.202,34.99 37.998,34.786 37.998,27.217 38.252,26.963 56.871,26.963 57.048,27.141 57.048,34.482 56.921,34.609 38.633,34.609 38.379,34.355 38.379,27.471 38.506,27.344 56.413,27.344 56.667,27.598 56.667,34.101 56.54,34.228 39.065,34.228 38.76,33.923 38.76,27.852 38.887,27.725 56.083,27.725 56.286,27.928 56.286,33.707 56.147,33.847 39.395,33.847 39.141,33.593 39.141,28.284 39.319,28.106 55.677,28.106 55.905,28.335 55.905,33.309 55.751,33.464 39.702,33.464 39.522,33.284 39.522,28.614 39.649,28.487 55.22,28.487 55.524,28.792 55.524,32.856 55.296,33.085 40.132,33.085 39.903,32.856 39.903,28.995 40.03,28.868 54.93,28.868 55.138,29.077 55.138,32.526 54.96,32.704 40.462,32.704 40.284,32.526 40.284,29.351 40.386,29.249 54.534,29.249 54.737,29.452 54.737,32.043 54.458,32.323 40.843,32.323 40.665,32.145 40.665,29.732 40.767,29.63 54.228,29.63 54.356,29.758 54.356,31.84 54.254,31.942 41.224,31.942 41.046,31.764 41.046,30.164 41.199,30.011 45.759,30.011 46.685,30.937 v3(46.685,30.988)
  GND w0.635: A7.1@44.323,40.03 44.323,42.545 45.136,43.358 59.639,43.358 61.874,41.123 v1(61.874,16.688)
  other v1: 61.874,17.348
